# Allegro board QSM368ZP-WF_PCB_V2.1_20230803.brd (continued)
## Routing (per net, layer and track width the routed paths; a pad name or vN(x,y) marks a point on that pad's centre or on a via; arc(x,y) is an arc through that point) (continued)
100OHM_LAN0_RJ45_D2P_A: length 18.2
  BOTTOM w0.092: J0901.4 108.46,9.34 108.35,9.22 107.87,9.22 107.55,9.55 107.55,11.19 106.73,12 106.73,18.41 103.85,21.3 103.85,23.2 103.92,23.28 103.92,24.29 U0901.19
100OHM_LAN0_RJ45_D3M_A: length 18.2
  BOTTOM w0.092: U0901.23 99.92,24.25 99.92,23.28 100.32,22.88 100.32,22.6 100.2,22.49 100.2,22.21 100.32,22.09 100.32,21.58 105.29,16.61 105.29,9.67 105.17,9.55 104.94,9.55 J0901.8
100OHM_LAN0_RJ45_D3P_A: length 18.2
  BOTTOM w0.092: J0901.7 105.4,9.48 105.5,9.58 105.5,16.7 100.53,21.67 100.53,22.88 100.92,23.28 100.92,24.25 U0901.22
100OHM_MIPI_CSI_RX_CLK0N: length 55.3
  TOP w0.092: R0258.1 93.53,91.67 93.62,91.58 U0207.1 93.62,91.08 93.81,90.89 93.81,89.99 93.66,89.83 93.47,89.83 93.37,89.93 93.37,90.21 93.28,90.3 93.1,90.3 93.01,90.21 93.01,89.93 92.91,89.83 92.73,89.83 92.64,89.93 92.64,90.21 92.55,90.3 92.36,90.3 92.27,90.21 92.27,89.93 92.18,89.83 91.89,89.83 91.8,89.93 91.8,90.64 91.59,90.85 91.23,90.85 91.01,90.64 91.01,90.07 90.92,89.97 88.33,89.97 86.66,88.3 86.66,77.84 84.63,75.82 72.45,75.82 71.19,74.56 70.64,74.56 70.55,74.65 70.55,75.19 70.33,75.4 69.97,75.4 69.76,75.19 69.76,74.65 69.67,74.56 69.48,74.56 69.39,74.65 69.39,75.19 69.18,75.4 68.82,75.4 68.6,75.19 68.6,74.65 68.51,74.56 68.33,74.56 68.24,74.65 68.24,75.19 68.02,75.4 67.66,75.4 67.45,75.19 67.45,74.65 67.36,74.56 66.41,74.56 66.19,74.34 66.19,74.04 66.07,73.92 66.07,73.65 66.19,73.53 66.19,73.25 66.07,73.14 66.07,72.86 66.19,72.74 66.19,72.47 66.1,72.38 65.1,72.38 65.01,72.28 64.78,72.28 64.6,72.47 64.6,73.11 64.77,73.28 U1301.2
100OHM_MIPI_CSI_RX_CLK0N1: length 5.8
  TOP w0.092: R0258.2 93.5,92.58 93.62,92.7 U0207.3 93.62,93.17 94.06,93.61 94.06,93.79 93.95,93.9 93.63,93.9 93.51,93.78 93.23,93.78 93.11,93.9 92.84,93.9 92.72,93.78 92.44,93.78 92.33,93.9 92.05,93.9 91.84,94.11 91.84,94.36 91.75,94.45 J0201.20
100OHM_MIPI_CSI_RX_CLK0P: length 52.9
  TOP w0.092: R0257.1 94.28,91.67 94.17,91.58 U0207.2 94.17,91.08 94.03,90.92 94.03,89.9 93.75,89.62 91.81,89.62 91.59,89.84 91.59,90.55 91.5,90.64 91.32,90.64 91.22,90.55 91.22,89.98 91.01,89.77 88.41,89.77 86.87,88.22 86.87,77.76 84.72,75.61 72.53,75.61 71.28,74.35 70.55,74.35 70.34,74.56 70.34,75.1 70.25,75.19 70.06,75.19 69.97,75.1 69.97,74.56 69.75,74.35 69.4,74.35 69.18,74.56 69.18,75.1 69.09,75.19 68.91,75.19 68.81,75.1 68.81,74.56 68.6,74.35 68.24,74.35 68.03,74.56 68.03,75.1 67.93,75.19 67.75,75.19 67.66,75.1 67.66,74.56 67.44,74.35 66.49,74.35 66.4,74.26 66.4,72.38 66.19,72.17 65.19,72.17 64.55,71.53 U1301.3
100OHM_MIPI_CSI_RX_CLK0P1: length 8.3
  TOP w0.092: R0257.2 94.29,92.58 94.17,92.69 U0207.4 94.17,93.43 94.27,93.52 94.27,93.88 94.04,94.11 92.14,94.11 92.05,94.2 J0201.19
100OHM_MIPI_CSI_RX_CLK1N: length 56.8
  TOP w0.092: 83.88,91.78 82.83,91.78 82.72,91.67 82.72,91.2 82.39,90.86 82.39,90.33 81.99,89.94 81.69,89.94 80.8,90.83 80.67,90.83 80.54,90.69 80.54,90.56 81.43,89.68 81.43,89.38 81.17,89.12 80.87,89.12 79.63,90.36 79.5,90.36 79.37,90.23 79.37,90.1 80.61,88.86 80.61,88.56 79.69,87.64 79.38,87.64 78.95,88.07 78.82,88.07 78.69,87.94 78.69,87.81 79.21,87.29 79.21,86.72 79,86.5 78.2,86.5 78.11,86.41 78.11,86.23 78.2,86.13 79,86.13 79.21,85.92 79.21,85.56 79,85.35 78.2,85.35 78.11,85.25 78.11,85.07 78.2,84.98 79,84.98 79.21,84.76 79.21,84.41 79,84.19 78.2,84.19 78.11,84.1 78.11,83.91 78.2,83.82 79,83.82 79.21,83.61 79.21,83.06 77.19,81.04 69.94,81.04 64.8,75.9 61.17,75.9 60.94,75.67 60.94,75.54 61.06,75.42 61.06,75.29 60.93,75.16 60.8,75.16 60.68,75.28 60.55,75.28 60.42,75.15 60.42,75.02 60.54,74.9 60.54,74.77 60.41,74.64 60.28,74.64 60.16,74.76 60.03,74.76 59.76,74.49 59.76,74.16 59.88,74.04 59.88,73.77 59.76,73.65 59.76,73.37 59.88,73.25 59.88,72.98 59.76,72.86 59.76,72.58 59.12,71.95 59.12,70.85 59.62,70.36 60.29,70.36 60.46,70.53 60.62,70.53 61.09,70.06 61.26,70.06 61.46,69.86 61.46,69.69 61.67,69.47 U1301.6
100OHM_MIPI_CSI_RX_CLK1N1: length 4.5
  TOP w0.092: R0264.2 82.82,92.67 82.72,92.77 82.72,93.45 82.56,93.61 81.89,93.61 81.63,93.87 81.63,94.03 81.44,94.23 81.27,94.23 81.08,94.42 J0202.20
100OHM_MIPI_CSI_RX_CLK1P: length 54
  TOP w0.092: U1301.9 60.55,69.67 60.08,70.15 59.53,70.15 58.91,70.76 58.91,72.04 59.55,72.67 59.55,74.58 61.09,76.11 64.71,76.11 69.85,81.25 77.1,81.25 79,83.15 79,83.52 78.91,83.61 78.11,83.61 77.9,83.83 77.9,84.19 78.11,84.4 78.91,84.4 79,84.49 79,84.68 78.91,84.77 78.11,84.77 77.9,84.98 77.9,85.34 78.11,85.56 78.91,85.56 79,85.65 79,85.83 78.91,85.92 78.11,85.92 77.9,86.14 77.9,86.5 78.11,86.71 78.91,86.71 79,86.8 79,87.2 78.48,87.73 78.48,88.03 78.73,88.28 79.04,88.28 79.47,87.85 79.6,87.85 80.4,88.65 80.4,88.78 79.16,90.01 79.16,90.31 79.42,90.57 79.72,90.57 80.96,89.33 81.09,89.33 81.22,89.46 81.22,89.59 80.33,90.48 80.33,90.78 80.59,91.04 80.89,91.04 81.77,90.15 81.9,90.15 82.17,90.42 U0208.1 82.17,91.68 82.08,91.78 81.03,91.78
100OHM_MIPI_CSI_RX_CLK1P1: length 7.1
  TOP w0.092: J0202.19 81.38,95.92 80.78,95.33 80.78,94.43 81.8,93.4 82.05,93.4 82.17,93.28 U0208.3 82.17,92.78 82.08,92.67 R0263.2
100OHM_MIPI_CSI_RX_D0N: length 56.9
  TOP w0.092: U1301.7 62.15,72.75 61.77,72.37 61.77,72.18 61.85,72.1 62.15,72.1 62.89,72.84 62.89,74.09 63.51,74.71 65.31,74.71 67.06,76.46 68.2,76.46 68.29,76.55 68.29,76.89 68.51,77.1 68.87,77.1 69.08,76.89 69.08,76.35 69.17,76.26 69.36,76.26 69.45,76.35 69.45,76.89 69.66,77.1 70.02,77.1 70.24,76.89 70.24,76.35 70.33,76.26 70.51,76.26 70.6,76.35 70.6,76.89 70.82,77.1 71.18,77.1 71.39,76.89 71.39,76.35 71.48,76.26 71.61,76.26 71.88,76.53 72.04,76.53 72.13,76.62 72.13,77.26 72.34,77.47 72.7,77.47 72.92,77.26 72.92,76.62 73.01,76.53 73.19,76.53 73.28,76.62 73.28,77.26 73.5,77.47 73.86,77.47 74.07,77.26 74.07,76.62 74.16,76.53 74.35,76.53 74.44,76.62 74.44,77.26 74.65,77.47 75.01,77.47 75.23,77.26 75.23,76.62 75.32,76.53 84.26,76.53 85.89,78.15 85.89,88.56 86.13,88.8 86.13,88.93 85.89,89.16 85.89,89.29 86.02,89.42 86.15,89.42 86.39,89.19 86.52,89.19 86.65,89.32 86.65,89.45 86.41,89.68 86.41,89.81 86.54,89.94 86.67,89.94 86.91,89.71 87.04,89.71 87.17,89.84 87.17,89.97 86.93,90.2 86.93,90.33 87.06,90.46 87.19,90.46 87.43,90.23 87.56,90.23 88.06,90.73 89.84,90.73 90,90.9 90,91.38 U0209.1 89.92,91.58 89.83,91.67 R0260.1
100OHM_MIPI_CSI_RX_D0N1: length 4.4
  TOP w0.092: J0201.22 91.15,94.47 91.24,94.39 91.24,94.04 91.14,93.94 90.48,93.94 90.27,93.72 90.27,93.31 90.2,93.25 90.03,93.25 89.92,93.15 U0209.3 89.92,92.67 89.83,92.58 R0260.2
100OHM_MIPI_CSI_RX_D0P: length 54.4
  TOP w0.092: R0259.1 90.57,91.67 90.47,91.58 U0209.2 90.47,91.08 89.92,90.53 88.15,90.53 86.1,88.47 86.1,78.06 84.35,76.31 75.23,76.31 75.02,76.53 75.02,77.17 74.93,77.27 74.74,77.27 74.65,77.17 74.65,76.53 74.43,76.31 74.08,76.31 73.86,76.53 73.86,77.17 73.77,77.27 73.59,77.27 73.49,77.17 73.49,76.53 73.28,76.31 72.92,76.31 72.71,76.53 72.71,77.17 72.61,77.27 72.43,77.27 72.34,77.17 72.34,76.53 72.12,76.31 71.96,76.31 71.7,76.05 71.4,76.05 71.18,76.27 71.18,76.8 71.09,76.89 70.91,76.89 70.81,76.8 70.81,76.27 70.6,76.05 70.24,76.05 70.03,76.27 70.03,76.8 69.93,76.89 69.75,76.89 69.66,76.8 69.66,76.27 69.44,76.05 69.09,76.05 68.87,76.27 68.87,76.8 68.78,76.89 68.59,76.89 68.5,76.8 68.5,76.47 68.29,76.25 67.15,76.25 65.4,74.5 63.6,74.5 63.1,74 63.1,72.75 62.24,71.89 61.99,71.89 61.92,71.82 61.92,71.58 61.73,71.38 U1301.8
100OHM_MIPI_CSI_RX_D0P1: length 7
  TOP w0.092: J0201.21 91.45,93.95 91.22,93.72 90.57,93.72 90.47,93.63 U0209.4 90.47,92.67 90.57,92.58 R0259.2
100OHM_MIPI_CSI_RX_D1N: length 52.5
  TOP w0.092: U1301.4 63.75,70.65 63.96,70.44 65.16,70.44 66.61,71.89 67.09,71.89 68.98,73.78 71.88,73.78 73.19,75.08 84.93,75.08 87.39,77.54 87.39,86.51 90.01,89.14 95.05,89.14 95.17,89.25 95.44,89.25 95.56,89.14 95.84,89.14 96.38,89.67 96.38,89.84 96.57,90.03 96.74,90.03 96.93,90.23 96.93,90.4 97.13,90.59 97.29,90.59 97.49,90.79 97.49,90.94 97.33,91.1 U0206.1 97.33,91.55 97.2,91.67 R0256.1
100OHM_MIPI_CSI_RX_D1N1: length 8.9
  TOP w0.092: J0201.10 94.75,95.75 95.05,96.05 95.33,96.05 95.44,95.93 95.72,95.93 95.84,96.05 96.11,96.05 96.23,95.93 96.51,95.93 96.63,96.05 97.17,96.05 97.92,95.31 97.92,94.91 97.8,94.79 97.8,94.51 97.92,94.39 97.92,94.02 97.67,93.77 97.67,93.39 97.57,93.3 97.5,93.3 97.33,93.13 U0206.3 97.33,92.67 97.22,92.58 R0256.2
100OHM_MIPI_CSI_RX_D1P: length 52.9
  TOP w0.092: R0255.1 98,91.67 97.88,91.55 U0206.2 97.88,91.1 97.7,90.92 97.7,90.7 95.92,88.92 90.1,88.92 87.6,86.42 87.6,77.45 85.02,74.88 73.28,74.88 71.97,73.56 69.06,73.56 67.17,71.67 66.7,71.67 65.25,70.22 63.88,70.22 63.54,70.56 63.54,72.01 63.45,72.1 63.12,72.1 62.95,71.92 U1301.5
100OHM_MIPI_CSI_RX_D1P1: length 8.6
  TOP w0.092: R0255.2 98,92.58 97.88,92.7 U0206.4 97.88,93.68 98.12,93.93 98.12,95.4 97.26,96.26 95.49,96.26 95.05,96.7 J0201.9
100OHM_MIPI_CSI_RX_D2N: length 53.9
  TOP w0.092: 80.17,91.78 79.15,91.78 79.03,91.65 U0201.2 79.03,91.2 78.85,91.03 78.85,90.78 78.64,90.56 77.2,90.56 77.11,90.47 77.11,90.26 77.2,90.17 78.33,90.17 78.55,89.95 78.55,89.6 78.33,89.38 77.2,89.38 77.11,89.29 77.11,89.1 77.2,89.01 77.98,89.01 78.2,88.8 78.2,88.44 77.98,88.22 77.2,88.22 77.11,88.13 77.11,84.64 76.55,84.08 76.55,83.95 77.3,83.2 77.3,82.9 77.05,82.65 76.74,82.65 76,83.39 75.87,83.39 75.74,83.26 75.74,83.13 76.48,82.39 76.48,82.08 76.23,81.83 75.92,81.83 75.18,82.57 75.05,82.57 74.22,81.75 69.65,81.75 64.75,76.85 64.17,76.85 63.88,77.14 63.7,77.14 63.6,77.05 63.6,76.84 63.39,76.62 63.03,76.62 62.82,76.84 62.82,77.05 62.72,77.14 62.54,77.14 62.45,77.05 62.45,76.84 62.23,76.62 61.87,76.62 61.66,76.84 61.66,77.05 61.57,77.14 61.38,77.14 61.29,77.05 61.29,76.84 61.08,76.62 60.88,76.62 60.71,76.46 60.41,76.46 59.71,77.16 59.58,77.16 59.45,77.03 59.45,76.9 60.15,76.2 60.15,75.9 59.9,75.65 59.59,75.65 58.35,76.89 58.22,76.89 58.09,76.76 58.09,76.63 59.33,75.39 59.33,75.08 59.08,74.83 58.77,74.83 58.52,75.09 58.39,75.09 58.25,74.96 58.25,74.83 58.51,74.57 58.51,74.26 58.36,74.11 58.36,72.47 58.5,72.33 58.77,72.33 58.95,72.5 U1301.16
100OHM_MIPI_CSI_RX_D2N1: length 7.5
  TOP w0.092: R0266.2 79.12,92.67 79.03,92.78 U0201.4 79.03,93.28 78.88,93.42 78.88,94.17 78.99,94.29 78.99,94.57 78.88,94.69 78.88,94.96 78.99,95.08 78.99,95.36 78.88,95.47 78.88,95.75 79.27,96.14 79.54,96.14 79.66,96.02 79.94,96.02 80.06,96.14 80.38,96.14 80.47,96.05 J0202.22
100OHM_MIPI_CSI_RX_D2P: length 53.5
  TOP w0.092: U1301.17 58.15,74.2 58.3,74.35 58.3,74.48 58.04,74.74 58.04,75.04 58.3,75.3 58.6,75.3 58.86,75.04 58.99,75.04 59.12,75.17 59.12,75.3 57.88,76.55 57.88,76.85 58.13,77.1 58.43,77.1 59.68,75.86 59.81,75.86 59.94,75.99 59.94,76.12 59.24,76.81 59.24,77.12 59.5,77.37 59.8,77.37 60.5,76.67 60.63,76.67 60.79,76.83 60.99,76.83 61.08,76.93 61.08,77.14 61.3,77.35 61.65,77.35 61.87,77.14 61.87,76.93 61.96,76.83 62.15,76.83 62.24,76.93 62.24,77.14 62.45,77.35 62.81,77.35 63.03,77.14 63.03,76.93 63.12,76.83 63.3,76.83 63.39,76.93 63.39,77.14 63.61,77.35 63.97,77.35 64.26,77.06 64.66,77.06 69.56,81.96 74.14,81.96 74.96,82.78 75.27,82.78 76.01,82.04 76.14,82.04 76.27,82.17 76.27,82.3 75.53,83.04 75.53,83.35 75.78,83.6 76.08,83.6 76.83,82.86 76.96,82.86 77.09,82.99 77.09,83.12 76.34,83.86 76.34,84.17 76.9,84.72 76.9,88.22 77.11,88.43 77.9,88.43 77.99,88.53 77.99,88.71 77.9,88.8 77.11,88.8 76.9,89.02 76.9,89.38 77.11,89.59 78.25,89.59 78.34,89.68 78.34,89.87 78.25,89.96 77.11,89.96 76.9,90.17 76.9,90.56 77.11,90.78 78.55,90.78 78.64,90.87 78.64,91.03 78.47,91.2 U0201.1 78.47,91.65 78.35,91.78 77.33,91.78
100OHM_MIPI_CSI_RX_D2P1: length 7.8
  TOP w0.092: R0265.2 78.38,92.67 78.47,92.78 U0201.3 78.47,93.25 78.67,93.44 78.67,95.84 79.18,96.35 80.42,96.35 80.78,96.7 80.78,97.75
100OHM_MIPI_CSI_RX_D3N: length 52.3
  TOP w0.092: 84.72,91.78 85.78,91.78 85.88,91.68 U0210.1 85.88,90.88 85.09,90.09 85.09,83.74 84.8,83.45 80.6,83.45 77.16,80.01 76.8,80.01 76.58,79.8 76.58,79.3 76.49,79.21 76.31,79.21 76.22,79.3 76.22,79.8 76,80.01 75.64,80.01 75.43,79.8 75.43,79.3 75.34,79.21 75.15,79.21 75.06,79.3 75.06,79.8 74.85,80.01 74.09,80.01 73.97,80.13 73.69,80.13 73.58,80.01 73.3,80.01 73.18,80.13 72.91,80.13 72.79,80.01 72.2,80.01 71.85,79.66 71.67,79.66 71.58,79.75 71.58,80.28 71.36,80.5 70.1,80.5 69.85,80.25 69.85,79.95 70.9,78.9 70.9,78.77 70.77,78.64 70.64,78.64 69.59,79.69 69.29,79.69 69.04,79.43 69.04,79.13 70.08,78.08 70.08,77.95 69.95,77.82 69.82,77.82 68.78,78.87 68.47,78.87 68.22,78.62 68.22,78.31 68.46,78.07 68.46,77.94 68.33,77.81 68.2,77.81 67.96,78.05 67.65,78.05 65.01,75.41 62.74,75.41 62.5,75.17 62.24,75.17 62.1,75.03 62.1,74.78 61.97,74.65 61.84,74.65 61.76,74.73 61.63,74.73 61.5,74.6 61.5,74.47 61.58,74.39 61.58,74.26 61.34,74.01 61.34,73.55 61.22,73.43 61.22,73.16 61.34,73.04 61.34,72.76 60.93,72.35 60.48,72.35 60.38,72.45 60.38,72.58 60.55,72.75 U1301.11
100OHM_MIPI_CSI_RX_D3N1: length 9.1
  TOP w0.092: R0262.2 85.78,92.67 85.88,92.78 U0210.3 85.88,93.25 86.06,93.43 86.06,93.68 86.36,93.98 86.81,93.98 87.17,94.34 87.17,94.74 87.05,94.86 87.05,95.14 87.17,95.26 87.17,95.53 86.71,95.99 86.42,95.99 86.3,95.87 86.02,95.87 85.9,95.99 85.63,95.99 85.51,95.87 85.23,95.87 85.12,95.99 84.84,95.99 84.64,95.79 84.64,95.63 84.45,95.43 84.28,95.43 84.08,95.22 J0202.10
100OHM_MIPI_CSI_RX_D3P: length 52.1
  TOP w0.092: 87.58,91.78 86.55,91.78 86.42,91.65 86.42,91.13 85.3,90 85.3,83.65 84.89,83.24 80.69,83.24 77.25,79.8 76.89,79.8 76.79,79.71 76.79,79.22 76.58,79 76.22,79 76.01,79.22 76.01,79.71 75.91,79.8 75.73,79.8 75.64,79.71 75.64,79.22 75.42,79 75.07,79 74.85,79.22 74.85,79.71 74.76,79.8 72.29,79.8 71.94,79.45 71.58,79.45 71.37,79.67 71.37,80.2 71.28,80.29 70.19,80.29 70.06,80.16 70.06,80.03 71.11,78.99 71.11,78.69 70.86,78.43 70.55,78.43 69.51,79.48 69.38,79.48 69.25,79.35 69.25,79.22 70.29,78.17 70.29,77.87 70.04,77.61 69.73,77.61 68.69,78.66 68.56,78.66 68.43,78.53 68.43,78.4 68.67,78.15 68.67,77.85 68.42,77.6 68.12,77.6 67.87,77.84 67.74,77.84 65.1,75.2 62.83,75.2 61.55,73.92 61.55,72.67 61.02,72.14 60.49,72.14 60.35,72 60.35,71.59 60.13,71.38 U1301.12
100OHM_MIPI_CSI_RX_D3P1: length 9.2
  TOP w0.092: J0202.9 84.38,96.85 85.03,96.2 86.8,96.2 87.38,95.62 87.38,94.25 86.9,93.78 86.45,93.78 86.27,93.59 86.27,93.41 86.42,93.25 86.42,92.8 86.55,92.67 R0261.2
100OHM_MIPI_DSI_TX0_CLKN: length 39.2
  TOP w0.092: U1301.37 51.75,75.37 56.34,79.96 56.34,84.81 56.25,84.9 55.44,84.9 55.23,85.11 55.23,85.47 55.44,85.69 56.25,85.69 56.34,85.78 56.34,85.96 56.25,86.05 55.44,86.05 55.23,86.27 55.23,86.63 55.44,86.84 56.25,86.84 56.34,86.93 56.34,87.12 56.25,87.21 55.44,87.21 55.23,87.42 55.23,87.78 55.44,88 56.25,88 56.34,88.09 56.34,88.34 56.25,88.43 55.87,88.43 55.65,88.65 55.65,89.01 55.87,89.22 56.25,89.22 56.34,89.31 56.34,89.72 58.9,92.28 59.45,92.28 61.05,93.88 63.13,93.88 63.25,93.99 63.25,96.17 63.35,96.28 J0403.17
100OHM_MIPI_DSI_TX0_CLKP: length 39
  TOP w0.092: J0403.18 63.85,96.07 63.77,96.15 63.52,96.15 63.46,96.09 63.46,93.9 63.22,93.67 61.14,93.67 59.54,92.06 58.99,92.06 56.55,89.63 56.55,89.23 56.34,89.01 55.95,89.01 55.86,88.92 55.86,88.74 55.95,88.64 56.34,88.64 56.55,88.43 56.55,88 56.34,87.79 55.53,87.79 55.44,87.69 55.44,87.51 55.53,87.42 56.34,87.42 56.55,87.2 56.55,86.85 56.34,86.63 55.53,86.63 55.44,86.54 55.44,86.36 55.53,86.26 56.34,86.26 56.55,86.05 56.55,85.69 56.34,85.47 55.53,85.47 55.44,85.38 55.44,85.2 55.53,85.11 56.34,85.11 56.55,84.89 56.55,79.88 51.96,75.28 51.96,72.69 52.15,72.5 52.42,72.5 52.55,72.63 U1301.36
100OHM_MIPI_DSI_TX0_D0N: length 39.3
  TOP w0.092: U1301.47 48.55,74.17 53.64,79.26 53.64,83.15 53.55,83.25 53.29,83.25 53.08,83.46 53.08,83.82 53.29,84.03 53.55,84.03 53.64,84.13 53.64,84.31 53.55,84.4 53.27,84.4 53.05,84.62 53.05,84.97 53.27,85.19 53.55,85.19 53.64,85.28 53.64,85.76 53.55,85.86 52.62,85.86 52.4,86.07 52.4,86.43 52.62,86.64 53.55,86.64 53.64,86.74 53.64,86.92 53.55,87.01 52.62,87.01 52.4,87.23 52.4,87.58 52.62,87.8 53.55,87.8 53.64,87.89 53.64,88.08 53.55,88.17 52.62,88.17 52.4,88.38 52.4,88.74 52.62,88.96 53.55,88.96 53.64,89.05 53.64,89.24 56.44,92.04 56.44,92.2 56.63,92.4 56.8,92.4 57,92.6 57,92.76 57.19,92.96 57.36,92.96 57.55,93.15 57.55,93.32 57.75,93.51 57.91,93.51 58.11,93.71 58.81,93.71 59.24,94.14 59.24,96.13 59.15,96.22 58.95,96.22 58.85,96.12 J0403.8
100OHM_MIPI_DSI_TX0_D0P: length 39.2
  TOP w0.092: U1301.46 49.35,72.57 49.26,72.47 48.85,72.47 48.76,72.57 48.76,74.08 53.85,79.17 53.85,83.24 53.63,83.46 53.38,83.46 53.28,83.55 53.28,83.73 53.38,83.82 53.63,83.82 53.85,84.04 53.85,84.4 53.63,84.61 53.35,84.61 53.26,84.7 53.26,84.89 53.35,84.98 53.63,84.98 53.85,85.19 53.85,85.85 53.63,86.07 52.7,86.07 52.61,86.16 52.61,86.34 52.7,86.43 53.63,86.43 53.85,86.65 53.85,87.01 53.63,87.22 52.7,87.22 52.61,87.31 52.61,87.5 52.7,87.59 53.63,87.59 53.85,87.8 53.85,88.16 53.63,88.38 52.7,88.38 52.61,88.47 52.61,88.65 52.7,88.75 53.63,88.75 53.85,88.96 53.85,89.15 58.2,93.5 58.9,93.5 59.45,94.05 59.45,96.34 59.35,96.44 J0403.9
100OHM_MIPI_DSI_TX0_D1N: length 38.5
  TOP w0.092: J0403.11 60.35,96.3 60.25,96.2 60.25,94.17 59.09,93.01 58.51,93.01 54.34,88.84 54.34,83.97 54.55,83.75 55.5,83.75 55.59,83.66 55.59,83.47 55.5,83.38 54.55,83.38 54.34,83.17 54.34,82.81 54.55,82.59 55.5,82.59 55.59,82.5 55.59,82.32 55.5,82.23 54.55,82.23 54.34,82.01 54.34,81.65 54.55,81.44 55.5,81.44 55.59,81.35 55.59,81.16 55.5,81.07 54.55,81.07 54.34,80.86 54.34,80.41 54.55,80.2 55.1,80.2 55.19,80.1 55.19,79.92 55.1,79.83 54.55,79.83 54.34,79.61 54.34,78.96 50.15,74.77 U1301.42
100OHM_MIPI_DSI_TX0_D1P: length 38.6
  TOP w0.092: J0403.12 60.85,96.12 60.76,96.21 60.56,96.21 60.46,96.11 60.46,94.08 59.18,92.8 58.6,92.8 54.55,88.75 54.55,84.05 54.64,83.96 55.59,83.96 55.8,83.75 55.8,83.39 55.59,83.17 54.64,83.17 54.55,83.08 54.55,82.9 54.64,82.8 55.59,82.8 55.8,82.59 55.8,82.23 55.59,82.02 54.64,82.02 54.55,81.92 54.55,81.74 54.64,81.65 55.59,81.65 55.8,81.43 55.8,81.08 55.59,80.86 54.64,80.86 54.55,80.77 54.55,80.5 54.64,80.41 55.19,80.41 55.4,80.19 55.4,79.83 55.19,79.62 54.64,79.62 54.55,79.53 54.55,78.88 50.36,74.69 50.36,72.54 50.45,72.45 50.83,72.45 50.95,72.58 U1301.41
100OHM_MIPI_DSI_TX0_D2N: length 39.3
  TOP w0.092: J0403.14 61.85,96.05 61.99,96.19 62.66,96.19 62.96,96.49 62.96,98.47 63.05,98.56 64.65,98.56 64.74,98.47 64.74,96.69 64.24,96.19 64.24,93.99 63.42,93.17 61.5,93.17 59.91,91.58 59.28,91.58 57.04,89.34 57.04,79.67 53.35,75.97 U1301.32
100OHM_MIPI_DSI_TX0_D2P: length 39.3
  TOP w0.092: J0403.15 62.35,96.5 62.45,96.4 62.58,96.4 62.75,96.58 62.75,98.56 62.97,98.78 64.73,98.78 64.95,98.56 64.95,96.6 64.45,96.1 64.45,93.9 63.51,92.97 61.59,92.97 60,91.38 59.37,91.38 57.25,89.25 57.25,79.58 53.56,75.89 53.56,72.69 53.65,72.6 54.06,72.6 54.15,72.69 U1301.31
100OHM_MIPI_DSI_TX0_D3N: length 39
  TOP w0.092: J0403.20 64.85,96.1 64.94,96.19 65.15,96.19 65.24,96.1 65.24,94 63.66,92.42 61.85,92.42 60.3,90.88 59.62,90.88 57.74,88.99 57.74,88.45 57.95,88.24 58.52,88.24 58.62,88.15 58.62,87.96 58.52,87.87 57.95,87.87 57.74,87.66 57.74,87.3 57.95,87.08 58.52,87.08 58.62,86.99 58.62,86.81 58.52,86.71 57.95,86.71 57.74,86.5 57.74,86.14 57.95,85.93 58.5,85.93 58.59,85.83 58.59,85.65 58.5,85.56 57.95,85.56 57.74,85.34 57.74,84.99 57.95,84.77 58.52,84.77 58.62,84.68 58.62,84.49 58.52,84.4 57.95,84.4 57.74,84.19 57.74,83.83 57.95,83.61 58.52,83.61 58.62,83.52 58.62,83.34 58.52,83.25 57.95,83.25 57.74,83.03 57.74,79.34 54.95,76.55 54.95,76.13 54.83,76.01 54.83,75.74 54.95,75.62 54.95,75.34 54.83,75.23 54.83,74.95 54.95,74.83 54.95,74.56 54.83,74.44 54.83,74.16 54.95,74.04 U1301.27
100OHM_MIPI_DSI_TX0_D3P: length 39
  TOP w0.092: J0403.21 65.45,97.47 65.45,93.91 63.75,92.22 61.94,92.22 60.39,90.67 59.71,90.67 57.95,88.9 57.95,88.54 58.04,88.45 58.61,88.45 58.83,88.23 58.83,87.88 58.61,87.66 58.04,87.66 57.95,87.57 57.95,87.38 58.04,87.29 58.61,87.29 58.83,87.08 58.83,86.72 58.61,86.5 58.04,86.5 57.95,86.41 57.95,86.23 58.04,86.14 58.59,86.14 58.8,85.92 58.8,85.56 58.59,85.35 58.04,85.35 57.95,85.26 57.95,85.07 58.04,84.98 58.61,84.98 58.83,84.77 58.83,84.41 58.61,84.19 58.04,84.19 57.95,84.1 57.95,83.92 58.04,83.82 58.61,83.82 58.83,83.61 58.83,83.25 58.61,83.04 58.04,83.04 57.95,82.94 57.95,79.25 55.16,76.46 55.16,72.54 55.25,72.45 55.57,72.45 55.75,72.63 U1301.26
100OHM_MIPI_DSI_TX1_CLKN: length 60.3
  TOP w0.092: v1(35.67,93.47) 35.62,93.53 D0506.2 35.92,94.25 36.15,94.47 R0575.1 ; U1301.33 52.55,68.72 52.64,68.62 v1(52.65,68.62)
  INNER LAYER 3 w0.074: v1(52.65,68.62) 52.8,68.78 52.8,69 52.67,69.12 52.67,69.34 52.8,69.47 52.8,69.69 52.67,69.82 52.67,70.04 52.8,70.17 52.8,70.39 52.67,70.52 52.67,70.74 52.8,70.86 52.8,71.07 52.73,71.14 52.27,71.14 52.08,71.33 52.08,71.65 52.27,71.84 52.73,71.84 52.8,71.91 52.8,72.13 52.73,72.2 49.09,72.2 45.75,75.54 45.75,75.87 45.68,75.94 44.79,75.94 44.6,76.13 44.6,76.44 44.79,76.64 45.68,76.64 45.75,76.71 45.75,76.86 45.68,76.93 44.79,76.93 44.6,77.12 44.6,77.44 44.79,77.63 45.68,77.63 45.75,77.7 45.75,77.85 45.68,77.92 44.79,77.92 44.6,78.12 44.6,78.43 44.79,78.62 45.68,78.62 45.75,78.69 45.75,78.84 45.68,78.92 44.79,78.92 44.6,79.11 44.6,79.42 44.79,79.61 45.68,79.61 45.75,79.69 45.75,79.83 45.68,79.91 44.79,79.91 44.6,80.1 44.6,80.41 44.79,80.6 45.68,80.6 45.75,80.68 45.75,80.83 45.68,80.9 44.79,80.9 44.6,81.09 44.6,81.41 44.79,81.6 45.68,81.6 45.75,81.67 45.75,81.82 45.68,81.89 44.79,81.89 44.6,82.08 44.6,82.4 44.79,82.59 45.68,82.59 45.75,82.66 45.75,82.81 45.68,82.88 44.79,82.88 44.6,83.08 44.6,83.39 44.79,83.58 45.68,83.58 45.75,83.65 45.75,83.8 45.68,83.88 44.79,83.88 44.6,84.07 44.6,84.38 44.79,84.57 45.68,84.57 45.75,84.65 45.75,84.79 45.68,84.87 44.79,84.87 44.6,85.06 44.6,85.37 44.79,85.56 45.68,85.56 45.75,85.64 45.75,85.84 38.38,93.21 38.21,93.21 38.05,93.36 38.05,93.54 37.89,93.7 37.67,93.7 37.54,93.57 37.32,93.57 37.2,93.7 36.86,93.7 36.74,93.57 36.51,93.57 36.39,93.7 35.9,93.7 v1(35.67,93.47)
100OHM_MIPI_DSI_TX1_CLKN_1: length 8.5
  TOP w0.092: R0575.2 35.75,95.38 35.62,95.5 D0506.4 35.62,95.96 35.53,96.05 35.44,96.05 35.3,96.19 35.3,96.42 35.05,96.67 34.49,96.67 34.37,96.79 34.1,96.79 33.98,96.67 33.7,96.67 33.25,96.22 33.25,95.94 33.13,95.82 33.13,95.54 33.25,95.42 33.25,95.15 32.99,94.89 32.4,94.89 32.28,95 32.01,95 31.89,94.89 31.61,94.89 31.44,95.06 31.44,95.21 31.48,95.25 J0501.30
100OHM_MIPI_DSI_TX1_CLKP: length 61
  TOP w0.092: R0574.1 34.55,94.47 34.78,94.25 D0506.1 35.08,93.53 v1(35.02,93.47) ; v1(53.27,68.42) 53.35,68.35 U1301.29
  INNER LAYER 3 w0.074: v1(35.02,93.47) 35.02,93.5 35.42,93.9 37.98,93.9 45.95,85.92 45.95,85.56 45.76,85.36 44.87,85.36 44.8,85.29 44.8,85.14 44.87,85.07 45.76,85.07 45.95,84.88 45.95,84.56 45.76,84.37 44.87,84.37 44.8,84.3 44.8,84.15 44.87,84.08 45.76,84.08 45.95,83.89 45.95,83.57 45.76,83.38 44.87,83.38 44.8,83.31 44.8,83.16 44.87,83.08 45.76,83.08 45.95,82.89 45.95,82.58 45.76,82.39 44.87,82.39 44.8,82.31 44.8,82.17 44.87,82.09 45.76,82.09 45.95,81.9 45.95,81.59 45.76,81.4 44.87,81.4 44.8,81.32 44.8,81.17 44.87,81.1 45.76,81.1 45.95,80.91 45.95,80.6 45.76,80.4 44.87,80.4 44.8,80.33 44.8,80.18 44.87,80.11 45.76,80.11 45.95,79.92 45.95,79.6 45.76,79.41 44.87,79.41 44.8,79.34 44.8,79.19 44.87,79.12 45.76,79.12 45.95,78.92 45.95,78.61 45.76,78.42 44.87,78.42 44.8,78.35 44.8,78.2 44.87,78.12 45.76,78.12 45.95,77.93 45.95,77.62 45.76,77.43 44.87,77.43 44.8,77.35 44.8,77.21 44.87,77.13 45.76,77.13 45.95,76.94 45.95,76.63 45.76,76.44 44.87,76.44 44.8,76.36 44.8,76.21 44.87,76.14 45.76,76.14 45.95,75.95 45.95,75.62 49.17,72.4 52.81,72.4 53,72.21 53,71.83 52.81,71.64 52.35,71.64 52.27,71.56 52.27,71.42 52.35,71.34 52.81,71.34 53,71.15 53,68.87 53.27,68.59 v1(53.27,68.42)
100OHM_MIPI_DSI_TX1_CLKP_1: length 8
  TOP w0.092: J0501.29 31.07,95.25 31.23,95.1 31.23,94.97 31.53,94.67 33.08,94.67 33.46,95.06 33.46,96.14 33.79,96.47 34.96,96.47 35.08,96.35 D0506.3 35.08,95.53 34.92,95.38 R0574.2
100OHM_MIPI_DSI_TX1_D0N: length 63.9
  TOP w0.092: v1(32.27,91.4) 32.27,91.45 32.17,91.55 D0502.2 32.17,92.15 32.27,92.25 R0573.1 ; v1(49.45,68.62) 49.44,68.62 49.35,68.72 U1301.43
  INNER LAYER 3 w0.074: v1(49.45,68.62) 49.6,68.78 49.6,69.67 49.44,69.83 48.94,69.83 48.86,69.75 48.86,69.07 48.67,68.88 48.36,68.88 48.17,69.07 48.17,69.75 48.09,69.83 47.37,69.83 47.17,70.02 47.17,71.12 46.98,71.31 46.88,71.31 45.64,70.08 45.37,70.08 45.15,70.3 45.15,70.57 46.38,71.8 46.38,71.91 46.28,72.01 46.17,72.01 44.94,70.78 44.67,70.78 44.45,71 44.45,71.27 45.68,72.51 45.68,72.61 45.58,72.72 45.47,72.72 44.24,71.48 43.97,71.48 43.75,71.7 43.75,71.97 44.98,73.21 44.98,73.31 44.87,73.42 44.77,73.42 44.04,72.68 43.77,72.68 43.54,72.91 43.54,73.18 44.28,73.91 44.28,74.01 43.4,74.89 43.4,86.44 42.82,87.02 42.72,87.02 42.12,86.42 41.85,86.42 41.63,86.64 41.63,86.91 42.23,87.51 42.23,87.61 42.08,87.77 41.97,87.77 41.39,87.18 41.12,87.18 40.9,87.4 40.9,87.68 41.48,88.26 41.48,88.36 41.37,88.47 41.27,88.47 40.69,87.88 40.42,87.88 40.19,88.11 40.19,88.38 40.78,88.96 40.78,89.06 40.67,89.17 40.57,89.17 39.98,88.59 39.71,88.59 39.49,88.81 39.49,89.08 40.08,89.66 40.08,89.77 39.97,89.87 39.87,89.87 39.28,89.29 39.01,89.29 38.79,89.51 38.79,89.78 39.37,90.36 39.37,90.47 37.92,91.92 36.64,91.92 36.52,91.8 36.29,91.8 36.17,91.92 35.95,91.92 35.82,91.8 35.6,91.8 35.47,91.92 35.25,91.92 35.12,91.8 34.9,91.8 34.78,91.92 34.55,91.92 34.43,91.8 34.21,91.8 34.08,91.92 33.86,91.92 33.73,91.8 33.51,91.8 33.38,91.92 33.16,91.92 33.04,91.8 32.81,91.8 32.69,91.92 32.11,91.92 32,91.82 32,91.47 32.07,91.4 v1(32.27,91.4)
100OHM_MIPI_DSI_TX1_D0N_1: length 5.2
  TOP w0.092: J0501.27 30.27,95.25 30.09,95.06 30.09,94.64 30.55,94.17 30.83,94.17 30.94,94.29 31.22,94.29 31.34,94.17 31.65,94.17 32.17,93.65 D0502.4 32.17,93.25 32.27,93.15 R0573.2
100OHM_MIPI_DSI_TX1_D0P: length 64.2
  TOP w0.092: U1301.39 50.15,68.35 v1(50.08,68.42) ; R0572.1 31.52,92.25 31.62,92.15 D0502.1 31.62,91.6 31.52,91.5 v1(31.52,91.4)
  INNER LAYER 3 w0.074: v1(50.08,68.42) 50.08,68.65 49.8,68.92 49.8,69.75 49.52,70.03 48.85,70.03 48.66,69.83 48.66,69.15 48.59,69.08 48.44,69.08 48.37,69.15 48.37,69.83 48.17,70.03 47.45,70.03 47.38,70.1 47.38,71.2 47.06,71.51 46.79,71.51 45.56,70.28 45.45,70.28 45.35,70.38 45.35,70.49 46.58,71.72 46.58,71.99 46.36,72.21 46.09,72.21 44.86,70.98 44.75,70.98 44.65,71.09 44.65,71.19 45.88,72.42 45.88,72.69 45.66,72.92 45.39,72.92 44.16,71.68 44.05,71.68 43.95,71.79 43.95,71.89 45.18,73.13 45.18,73.4 44.96,73.62 44.69,73.62 43.95,72.88 43.85,72.88 43.74,72.99 43.74,73.09 44.48,73.83 44.48,74.1 43.6,74.97 43.6,86.53 42.91,87.22 42.64,87.22 42.04,86.62 41.94,86.62 41.83,86.73 41.83,86.83 42.43,87.43 42.43,87.7 42.16,87.97 41.89,87.97 41.3,87.38 41.2,87.38 41.1,87.49 41.1,87.59 41.68,88.18 41.68,88.45 41.46,88.67 41.19,88.67 40.6,88.08 40.5,88.08 40.39,88.19 40.39,88.29 40.98,88.88 40.98,89.15 40.76,89.37 40.48,89.37 39.9,88.79 39.8,88.79 39.69,88.89 39.69,89 40.28,89.58 40.28,89.85 40.05,90.07 39.78,90.07 39.2,89.49 39.09,89.49 38.99,89.59 38.99,89.7 39.57,90.28 39.57,90.55 38,92.12 32.02,92.12 31.8,91.9 31.8,91.47 31.73,91.4 v1(31.52,91.4)
100OHM_MIPI_DSI_TX1_D0P_1: length 4.8
  TOP w0.092: J0501.26 29.88,94.55 30.46,93.97 31.53,93.97 31.62,93.87 D0502.3 31.62,93.28 31.5,93.15 R0572.2
100OHM_MIPI_DSI_TX1_D1N: length 64.8
  TOP w0.092: v1(28.55,91.42) 28.48,91.5 28.48,92.15 28.57,92.25 R0571.1 ; v1(51.05,68.62) 51.04,68.62 50.95,68.72 U1301.38
  INNER LAYER 3 w0.074: v1(28.55,91.42) 28.27,91.69 28.27,91.87 28.43,92.03 28.6,92.03 28.76,92.18 28.76,92.36 28.92,92.52 29.1,92.52 29.25,92.67 29.25,92.85 29.5,93.1 29.72,93.1 29.79,93.03 29.79,91.57 29.99,91.38 30.3,91.38 30.49,91.57 30.49,93.03 30.56,93.1 30.71,93.1 30.79,93.03 30.79,92.49 30.98,92.3 31.29,92.3 31.48,92.49 31.48,93.03 31.56,93.1 32.08,93.1 32.65,92.53 32.98,92.53 33.17,92.72 33.17,93.8 33.25,93.88 33.4,93.88 33.47,93.8 33.47,92.72 33.66,92.53 38.19,92.53 44,86.72 44,75.24 44.13,75.11 44.4,75.11 44.62,75.32 44.72,75.32 44.83,75.22 44.83,75.11 44.61,74.9 44.61,74.63 44.84,74.41 45.11,74.41 45.47,74.77 45.57,74.77 45.68,74.66 45.68,74.56 45.32,74.2 45.32,73.93 45.54,73.7 45.81,73.7 46.17,74.07 46.27,74.07 46.38,73.96 46.38,73.86 46.02,73.5 46.02,73.22 46.24,73 46.51,73 46.87,73.37 46.98,73.37 47.08,73.26 47.08,73.16 46.72,72.79 46.72,72.52 46.94,72.3 47.21,72.3 47.57,72.66 47.68,72.66 47.78,72.56 47.78,72.45 47.42,72.09 47.42,71.82 47.64,71.6 47.8,71.6 47.88,71.53 47.88,70.67 48.07,70.47 48.38,70.47 48.57,70.67 48.57,71.53 48.65,71.6 48.8,71.6 48.87,71.53 48.87,70.67 49.06,70.47 49.38,70.47 49.57,70.67 49.57,71.53 49.64,71.6 49.79,71.6 49.86,71.53 49.86,70.67 50.05,70.47 50.37,70.47 50.56,70.67 50.56,71.53 50.63,71.6 50.77,71.6 51.23,71.13 51.23,70.96 51.39,70.8 51.57,70.8 51.85,70.52 51.85,70.24 51.72,70.11 51.72,69.89 51.85,69.76 51.85,69.42 51.57,69.14 51.39,69.14 51.23,68.99 51.23,68.81 v1(51.05,68.62)
100OHM_MIPI_DSI_TX1_D1N_1: length 4
  TOP w0.092: J0501.24 29.07,95.23 28.98,95.13 28.98,94.9 28.78,94.7 28.78,94.54 28.58,94.34 28.42,94.34 28.21,94.14 28.21,93.98 28.48,93.72 28.48,93.28 28.6,93.15 R0571.2
100OHM_MIPI_DSI_TX1_D1P: length 65.1
  TOP w0.092: R0570.1 27.82,92.25 27.93,92.15 D0512.1 27.93,91.53 v1(27.8,91.4) ; v1(51.67,68.42) 51.75,68.35 U1301.34
  INNER LAYER 3 w0.074: v1(51.67,68.42) 51.52,68.58 51.52,68.82 52.05,69.34 52.05,70.6 50.85,71.8 50.55,71.8 50.36,71.61 50.36,70.75 50.28,70.67 50.14,70.67 50.06,70.75 50.06,71.61 49.87,71.8 49.56,71.8 49.37,71.61 49.37,70.75 49.29,70.67 49.14,70.67 49.07,70.75 49.07,71.61 48.88,71.8 48.57,71.8 48.37,71.61 48.37,70.75 48.3,70.67 48.15,70.67 48.08,70.75 48.08,71.61 47.89,71.8 47.73,71.8 47.62,71.9 47.62,72.01 47.98,72.37 47.98,72.64 47.76,72.86 47.49,72.86 47.13,72.5 47.02,72.5 46.92,72.61 46.92,72.71 47.28,73.07 47.28,73.34 47.06,73.57 46.79,73.57 46.43,73.2 46.32,73.2 46.22,73.31 46.22,73.41 46.58,73.78 46.58,74.05 46.36,74.27 46.09,74.27 45.72,73.9 45.62,73.9 45.52,74.01 45.52,74.11 45.88,74.48 45.88,74.75 45.66,74.97 45.39,74.97 45.02,74.61 44.92,74.61 44.81,74.71 44.81,74.82 45.03,75.03 45.03,75.3 44.8,75.52 44.53,75.52 44.32,75.31 44.22,75.31 44.2,75.33 44.2,86.8 38.27,92.72 33.74,92.72 33.67,92.8 33.67,93.88 33.48,94.08 33.17,94.08 32.97,93.88 32.97,92.8 32.9,92.72 32.73,92.72 32.16,93.3 31.47,93.3 31.28,93.11 31.28,92.57 31.21,92.5 31.06,92.5 30.99,92.57 30.99,93.11 30.8,93.3 30.48,93.3 30.29,93.11 30.29,91.65 30.22,91.58 30.07,91.58 29.99,91.65 29.99,93.11 29.8,93.3 29.42,93.3 28.07,91.95 28.07,91.69 v1(27.8,91.4)
100OHM_MIPI_DSI_TX1_D1P_1: length 3.8
  TOP w0.092: R0570.2 27.81,93.15 27.93,93.27 D0512.3 27.93,93.72 28,93.8 28,94.22 28.77,94.99 28.77,95.13 28.68,95.22 J0501.23
100OHM_MIPI_DSI_TX1_D2N: length 63.1
  TOP w0.092: v1(54.25,68.62) 54.24,68.62 54.15,68.72 U1301.28 ; R0569.1 24.9,92.25 24.77,92.12 D0511.2 24.77,91.5 v1(24.88,91.4)
  INNER LAYER 3 w0.074: v1(24.88,91.4) 24.61,91.66 24.61,91.85 24.45,92 24.45,92.18 24.3,92.34 24.12,92.34 23.9,92.56 23.9,92.88 24.03,93.01 24.03,93.23 23.9,93.35 23.9,93.58 24.06,93.73 24.24,93.73 24.39,93.89 24.39,94.07 24.8,94.47 25.1,94.47 25.18,94.4 25.18,92.84 25.37,92.65 25.68,92.65 25.87,92.84 25.87,94.4 25.95,94.47 26.1,94.47 26.17,94.4 26.17,92.84 26.36,92.65 26.68,92.65 26.87,92.84 26.87,94.4 26.94,94.47 28.32,94.47 28.45,94.6 34.73,94.6 35,94.33 38.22,94.33 46.35,86.2 46.35,75.84 49.32,72.88 54.22,72.88 54.4,72.69 54.4,71.83 54.27,71.7 54.27,71.48 54.4,71.35 54.4,71.13 54.27,71 54.27,70.78 54.4,70.66 54.4,70.43 54.27,70.31 54.27,70.09 54.4,69.96 54.4,69.74 54.27,69.61 54.27,69.39 54.4,69.26 54.4,69.04 54.48,68.97 54.48,68.85 v1(54.25,68.62)
100OHM_MIPI_DSI_TX1_D2N_1: length 5.9
  TOP w0.092: R0569.2 24.9,93.15 24.77,93.28 D0511.4 24.77,93.85 24.82,93.89 26.51,93.89 26.76,94.14 26.93,94.14 27.12,94.33 27.12,94.5 27.32,94.7 27.48,94.7 27.68,94.89 27.68,95.06 27.88,95.25 J0501.21
100OHM_MIPI_DSI_TX1_D2P: length 63.1
  TOP w0.092: v1(54.88,68.42) 54.95,68.35 U1301.24 ; R0568.1 24.1,92.25 24.23,92.12 D0511.1 24.23,91.47 v1(24.18,91.42)
  INNER LAYER 3 w0.074: v1(54.88,68.42) 54.67,68.62 54.67,69.05 54.6,69.12 54.6,72.78 54.3,73.08 49.4,73.08 46.55,75.92 46.55,86.28 38.31,94.53 35.08,94.53 34.81,94.8 28.37,94.8 28.24,94.67 26.86,94.67 26.67,94.48 26.67,92.92 26.59,92.85 26.44,92.85 26.37,92.92 26.37,94.48 26.18,94.67 25.87,94.67 25.67,94.48 25.67,92.92 25.6,92.85 25.45,92.85 25.38,92.92 25.38,94.48 25.19,94.67 24.72,94.67 23.7,93.66 23.7,92.47 24.41,91.76 24.41,91.66 v1(24.18,91.42)
100OHM_MIPI_DSI_TX1_D2P_1: length 5.9
  TOP w0.092: J0501.20 27.48,95.15 26.43,94.1 24.62,94.1 24.23,93.7 D0511.3 24.23,93.25 24.12,93.15 R0568.2
100OHM_MIPI_DSI_TX1_D3N: length 59.5
  TOP w0.092: v1(55.85,68.62) 55.84,68.62 55.75,68.72 U1301.23 ; R0567.1 21.19,92.25 21.07,92.13 D0514.2 21.07,91.42 v1(21.12,91.38)
  INNER LAYER 3 w0.074: v1(55.85,68.62) 56.05,68.83 56.2,68.83 56.27,68.9 56.27,71.72 54.49,73.5 49.57,73.5 46.98,76.09 46.98,86.5 38.15,95.33 27.9,95.33 27.75,95.17 24.13,95.17 20.9,91.95 20.9,91.6 v1(21.12,91.38)
100OHM_MIPI_DSI_TX1_D3N_1: length 9.5
  TOP w0.092: J0501.18 26.68,95.3 26.56,95.18 26.56,95.01 26.27,94.72 25.99,94.72 25.87,94.6 25.59,94.6 25.48,94.72 25.2,94.72 25.08,94.6 24.81,94.6 24.69,94.72 24.41,94.72 24.3,94.6 24.02,94.6 23.9,94.72 23.62,94.72 23.51,94.6 23.23,94.6 23.11,94.72 22.84,94.72 22.72,94.6 22.44,94.6 22.32,94.72 22,94.72 21.88,94.6 21.61,94.6 21.49,94.72 21.21,94.72 20.91,94.41 20.91,93.89 21.07,93.72 D0514.4 21.07,93.24 21.17,93.15 R0567.2
100OHM_MIPI_DSI_TX1_D3P: length 60.1
  TOP w0.092: U1301.19 56.55,68.35 v1(56.48,68.42) ; v1(20.48,91.38) 20.52,91.42 20.52,92.13 20.41,92.25 R0566.1
  INNER LAYER 3 w0.074: v1(20.48,91.38) 20.7,91.6 20.7,92.03 24.04,95.38 27.67,95.38 27.82,95.53 38.23,95.53 47.17,86.58 47.17,76.18 49.65,73.7 54.58,73.7 56.48,71.8 v1(56.48,68.42)
100OHM_MIPI_DSI_TX1_D3P_1: length 8.9
  TOP w0.092: J0501.17 26.27,95.3 26.35,95.23 26.35,95.1 26.18,94.92 21.13,94.92 20.7,94.49 20.7,93.89 20.52,93.72 20.52,93.25 20.43,93.15 R0566.2
CAM0_AVDD: length 24.6
  TOP w0.3: J0201.16 92.95,95.25 93.08,95.38 v1(93.08,96.75)
  INNER LAYER 2 w0.3: v1(76.83,94.58) 77.15,94.9 77.15,98.1 77.75,98.7 82.05,98.7 82.35,99 82.8,99 83.1,98.7 92.72,98.7 93.15,98.28 93.15,96.83 v1(93.08,96.75)
  BOTTOM w0.3: v1(76.83,94.58) B0201.2
CAM0_DOVDD_1V8: length 25.3
  TOP w0.2: v1(93.95,98.65) 93.92,98.67 93.12,98.67 92.65,98.2 J0201.17
  BOTTOM w0.2: B0205.2 74.83,94.15 75.55,94.88 75.55,97.8 76.55,98.8 82.22,98.8 82.38,98.95 82.78,98.95 82.92,98.8 93.8,98.8 v1(93.95,98.65)
CAM0_PDN_L_GPIO3_D5: length 78.8
  TOP w0.1: J0201.24 v1(90.55,95.5) ; v1(99.4,82.25) 99.31,82.16 99.31,72.94 96.67,70.3 96.67,63.23 90.9,57.45 90.9,55.08 84.15,48.33 71,48.33 70.25,47.58 70.25,44.77 69.47,44 69.47,43.67 68.47,42.67 U1301.316
  INNER LAYER 3 w0.1: v1(90.55,95.5) 90.55,95.22 91.55,94.22 93.3,94.22 95.45,92.08 95.45,90.92 99.17,87.2 99.17,82.47 v1(99.4,82.25)
CAM0_RST_L_GPIO3_D4: length 78.6
  TOP w0.1: v1(98.55,79.88) 98.8,79.62 98.8,73.03 96.22,70.45 96.22,63.45 90.5,57.73 90.5,55.27 83.96,48.74 70.81,48.74 69.85,47.77 69.85,45 69.06,44.21 69.06,43.86 68.67,43.48 U1301.317 ; v1(93.67,95.53) 93.67,95.45 93.55,95.33 J0201.14
  INNER LAYER 3 w0.1: v1(93.67,95.53) 93.67,95.45 100.03,89.1 100.03,81.2 98.7,79.88 v1(98.55,79.88)
CAM1_AVDD: length 5.6
  TOP w0.3: 82.28,94.88 82.28,95.9 v1(82.08,96.1)
  BOTTOM w0.3: B0204.2 78.47,94.6 78.47,94.72 79.28,95.53 80.97,95.53 81.55,96.1 v1(82.08,96.1)
CAM1_DOVDD_1V8: length 11.6
  TOP w0.2: v1(82.03,97) 82.03,97.7 J0202.17
  BOTTOM w0.2: v1(82.03,97) 80.6,98.42 76.85,98.42 75.85,97.42 75.85,94.58 75.67,94.4 B0206.2
CAM1_MCLK: length 102.7
  TOP w0.1: v1(69.53,85.22) 71.83,85.22 73.33,86.72 75.03,86.72 76.35,88.05 76.35,93.17 77.03,93.85 78,93.85 78.22,94.08 78.22,95.2 v1(77.95,95.47) ; v1(78.65,72.03) 78.65,72.08 78.85,72.28 85.17,72.28 89.47,76.58 89.47,80.88 v1(89.7,81.1) ; v1(41.92,63.8) 40.52,63.8 39.65,64.67 38.85,64.67 38.15,65.38 U1301.75
  INNER LAYER 3 w0.1: v1(69.53,85.22) 69.78,85.22 73.72,81.28 80.51,81.28 81.06,80.72 89.33,80.72 v1(89.7,81.1) ; v1(41.92,63.8) 57.27,63.8 60.24,66.76 64.37,66.76 68.83,71.22 72.96,71.22 74.66,72.92 77.5,72.92 78.4,72.03 v1(78.65,72.03)
  BOTTOM w0.1: R0226.1 v1(77.95,95.47)
CAM1_PDN_L_GPIO3_D3: length 91.9
  TOP w0.1: U1301.313 67.1,42.67 67.7,43.27 68.78,43.27 69.28,43.77 69.28,44.1 70.05,44.88 70.05,47.67 70.9,48.52 84.05,48.52 90.7,55.17 90.7,57.6 96.45,63.35 96.45,70.38 99.03,72.95 99.03,81.65 v1(98.35,82.33) ; J0202.24 v1(79.88,94.17)
  INNER LAYER 3 w0.1: v1(98.35,82.33) 97.6,82.33 97.42,82.5 95.8,82.5 95.33,82.97 95.33,84.15 95.83,84.65 95.83,87.2 89.28,93.75 83.42,93.75 82.3,94.88 80.58,94.88 v1(79.88,94.17)
CAM1_RST_L_GPIO3_D2: length 89.7
  TOP w0.1: J0202.14 v1(82.88,95.55) ; U1301.314 65.33,43.48 65.55,43.7 65.55,44.12 65.78,44.35 67.22,44.35 67.72,44.85 69.25,44.85 69.45,45.05 69.45,47.7 70.72,48.98 83.9,48.98 90.3,55.37 90.3,57.83 96.03,63.55 96.03,70.6 97.7,72.28 97.7,82.65 v1(98.05,83)
  INNER LAYER 3 w0.1: v1(98.05,83) 97.5,83 97.2,82.7 95.9,82.7 95.53,83.08 95.53,83.95 96.05,84.47 96.05,87.28 89.38,93.95 85.25,93.95 84.05,95.15 83.62,95.15 83.22,95.55 v1(82.88,95.55)
CAM_DOVDD_1V8: length 28.1
  INNER LAYER 2 w0.2: v1(82.5,96.55) 82.5,97.78 83.08,98.35 87.28,98.35 87.47,98.15 v1(87.47,96.6)
  BOTTOM w0.1: B0205.1 R0212.2 C0299.1
  BOTTOM w0.2: R0222.2 R0221.2 R0207.2 R0208.2 87.75,96.88 v1(87.47,96.6) ; B0206.1 76.25,93.53 76.25,97.3 77.05,98.1 80.5,98.1 81.47,97.13 81.47,96.75 81.67,96.55 v1(82.5,96.55)
  BOTTOM w0.4: U0205.5 C0209.2 B0205.1 B0206.1
CEC_HDMI: length 12.1
  TOP w0.1: v1(8.1,12.45) 8.2,12.35 J0401.13
  BOTTOM w0.1: D0404.3 13.05,18.23 R0416.1 12.4,17.88 12.05,17.52 D0408.1 8.72,14.5 8.2,13.97 8.2,12.55 v1(8.1,12.45)
CMA0_MCLK: length 90.1
  TOP w0.1: v1(90.25,96.95) J0201.25 ; v1(95.97,83.53) 95.97,83.47 95.2,82.7 95.2,72.33 94.58,71.7 94.58,64.22 82.22,51.88 73.97,51.88 73.55,51.45 71.2,51.45 70.38,50.62 v1(70.38,50.25) ; U1301.279 v1(56.55,39.45)
  INNER LAYER 3 w0.1: v1(70.38,50.25) 70.05,50.25 69.2,49.4 64.7,49.4 61.92,46.62 61.92,44.95 56.55,39.58 v1(56.55,39.45) ; v1(90.25,96.95) 89.55,96.25 89.55,95.03 98.08,86.5 98.08,84 97.6,83.53 v1(95.97,83.53)
DBG_RXD: length 69.9
  TOP w0.1: J1201.23 113.42,89.72 110.25,89.72 109,88.47 90.35,88.47 88.21,86.34 88.21,77.29 85.29,74.36 73.89,74.36 71.72,72.2 70.74,72.2 69.34,70.8 67.42,70.8 66.65,70.03 65.72,70.03 63.02,67.33 63.02,65.1 62.65,64.72 U1301.378
DBG_TXD: length 71.2
  TOP w0.1: J1201.21 D1255.2 110.38,89.12 109.95,89.12 109.1,88.28 90.45,88.28 88.42,86.25 88.42,77.2 85.38,74.15 74.08,74.15 71.92,72 70.83,72 69.42,70.6 67.53,70.6 66.75,69.83 65.8,69.83 63.23,67.25 63.23,65.1 63.45,64.88 63.45,62.83 63.3,62.67 U1301.374
DC12V: length 154.5
  TOP w0.1: v1(50,86.53) 50.2,86.33 v1(50.2,82.25)
  TOP w0.2: v1(32.75,65.33) 33.8,64.28 v1(36.48,64.28) ; v1(22.75,86.95) v1(23.25,86.95)
  TOP w0.5: v1(10.3,82.58) 9.7,82.58 8.7,83.58 R0116.1 ; v1(10.8,82.58) 11.3,83.08 TP0102.1
  TOP w0.8: 3.5,45.45 6.95,48.9 6.95,79.03 10.12,82.2
  TOP w4: 24.95,86.6 25.57,85.97 42.48,85.97
  BOTTOM w0.1: R0113.2 v1(50.2,82.25) ; R0620.2 36.08,52.05 36.73,52.7 40.45,52.7 40.67,52.48
  BOTTOM w0.2: 24.57,86 24.55,85.97 24.55,82.95 25.27,82.22 R0104.2 ; R0117.2 v1(32.75,65.33) ; R0723.2 65.35,30.82 63.55,30.82 61.22,33.16 61.22,33.44
  BOTTOM w2: 40.9,49.73 40.88,49.7 ; 16.85,77.08 16.85,73.45
  BOTTOM w3: 37.52,66.55 37.52,69.83 41.5,73.8 41.5,83.33 ; 62.34,34.56 57.38,29.6 41.85,29.6 ; 37.83,39.03 40.95,42.15 40.95,48.83 ; 40.67,60.23 40.67,49.95
  vias: v1(3.3,45.45) v1(3.3,44.95) v1(22.75,87.45) v1(22.75,86.45) v1(22.75,85.95) v1(23.25,87.45) v1(23.25,86.45) v1(23.25,85.95) v1(40.67,84.9) v1(40.7,84.4) v1(41.17,84.9) v1(41.2,84.4) v1(41.67,84.9) v1(41.7,84.4) v1(50,87.03) v1(50.5,87.03) v1(50.5,86.53) v1(51,87.03) v1(51,86.53)
EDP_BL_EN: length 16.4
  BOTTOM w0.1: R0522.1 D0505.3 9.35,33.8 8.97,34.17 7.75,34.17 7.58,34 7.15,34 6.83,34.33 6.83,35.05 7.16,35.38 7.16,39.81 7.4,40.05 7.4,41.7 7.16,41.94 7.16,42.64 7.89,43.38 9.32,43.38
EDP_DET: length 68.8
  TOP w0.1: U1301.70 39.75,65.15 40.3,64.6 v1(41.17,64.6) ; v1(25.7,31.05) 23.82,31.05 v1(20.88,34)
  INNER LAYER 3 w0.1: v1(20.88,34) 20,34 15.53,38.48 15.53,41.58 16.98,43.02 16.98,44.38 v1(16.5,44.85) ; v1(42.77,53.88) 42.77,53.77 41.92,52.92 36.33,52.92 34.95,51.55 34.95,50.9 27,42.95 27,42.42 26.75,42.17 26.55,42.17 26.43,42.05 26.43,32.12 25.7,31.4 v1(25.7,31.05)
  BOTTOM w0.1: R0527.2 R0516.2 v1(16.5,44.85) ; v1(42.77,53.88) 42.77,61.02 41.17,62.62 v1(41.17,64.6)
EDP_HPD: length 3.3
  BOTTOM w0.1: 11.72,43.88 14.43,43.88 14.55,44 R0527.1
EDP_PWM: length 9.9
  BOTTOM w0.1: 10.32,35.27 9.32,35.27 9.32,35.67 7.88,37.12 7.88,41.95 8.3,42.38 9.32,42.38
EDP_VDDIN: length 9.2
  BOTTOM w0.1: 14.5,35.35 Q0501.3 13.95,35.3 13.47,34.83 12.78,34.83 12.75,34.85 R0525.2 12.2,34.9 12.57,35.27 R0506.2 R0522.2 ; 11.72,39.88 11.72,38.88 11.22,39.38 9.32,39.38
EDP_VLED: length 1.5
  BOTTOM w0.4: 9.32,52.38 7.8,52.38
ETH1_REFCLKO_25M_M1: length 75.6
  TOP w0.1: v1(112.4,41.2) 113.85,42.65 113.85,49.73 108.5,55.08 107.75,55.08 106.8,56.02 99.17,56.02 98.47,55.33 92.55,55.33 89.67,52.45 89.67,50 87.22,47.55 72.45,47.55 v1(72.15,47.25) ; U1301.288 v1(59.75,39.42)
  INNER LAYER 3 w0.1: v1(72.15,47.25) 71.97,47.25 71.2,46.48 68.5,46.48 62.3,40.27 60.6,40.27 v1(59.75,39.42)
  BOTTOM w0.1: R0925.2 v1(112.4,41.2)
EXT_EN: length 188.5
  TOP w0.1: v1(20.23,28.38) 20.23,27.77 25.43,22.57 25.7,22.57 v1(25.9,22.77) ; U1301.217 35.75,37.38 v1(35.58,37.55) ; v1(52.4,82.42) 52.4,82.25 51.67,81.53 47.8,81.53 46.27,83.05 32.6,83.05 30.43,80.88 15.8,80.88 12.75,83.92 12.75,85.1 11.43,86.42 7.22,86.42 6.17,85.38 6.17,52.95 2.12,48.9 2.12,43.85 6.7,39.27 6.7,30.8 7.25,30.25 7.25,29.62 7.12,29.5 v1(7.12,28.98)
  INNER LAYER 2 w0.1: v1(28.27,38.2) 28.35,38.2 28.82,37.73 34.5,37.73 34.73,37.95 35.17,37.95 v1(35.58,37.55)
  INNER LAYER 3 w0.1: v1(20.23,28.38) 20.23,28.57 19.73,29.07 7.22,29.07 v1(7.12,28.98)
  BOTTOM w0.1: R0644.2 33.08,49.02 28.38,44.33 28.38,38.3 v1(28.27,38.2) 27.95,37.88 27.95,31.9 27.18,31.12 27.18,26.32 26.45,25.6 26.45,23.05 26.18,22.77 v1(25.9,22.77)
  BOTTOM w0.2: R0166.2 51.85,82.42 v1(52.4,82.42) 54.75,82.42 55.12,82.8 62.33,82.8 62.98,83.45
FSPI_CS0N/FLASH_CS0N: length 63.3
  TOP w0.1: U1301.281 v1(55.75,33.85) ; v1(92.83,55.92) 92.8,55.95 92.58,55.95 89.25,52.62 89.25,50.17 87.03,47.95 71.5,47.95 71.03,47.48 v1(71.03,47.2)
  INNER LAYER 3 w0.1: v1(71.03,47.2) 70.75,46.92 68.28,46.92 62.23,40.88 60.17,40.88 59.15,39.85 59.15,37.33 58.85,37.02 57.45,37.02 56.73,37.75 56.33,37.75 55.75,37.17 v1(55.75,33.85)
  BOTTOM w0.1: R1125.2 99.45,56.85 98.33,55.73 93.03,55.73 v1(92.83,55.92)
FSPI_D0/FLASH_RDY: length 135.1
  TOP w0.1: U1301.267 51.75,33.95 51.85,33.85 53.02,33.85 53.35,33.52 53.35,31.82 53.65,31.52 55.25,31.52 62.67,24.1 64.55,24.1 v1(64.72,24.27) ; v1(12.62,5.4) 13.1,5.88 23.82,5.88 26.45,3.25 28.35,3.25 29.02,2.58 30.25,2.58 31,3.33 53.48,3.33 55.65,1.15 61.35,1.15 62.2,2 62.2,16.48 59.65,19.02 v1(59.65,19.57) ; v1(7.47,32.77) 7.53,32.73 7.53,28.65 7.2,28.32 7.2,26.6 1.32,20.73 1.32,14.07 v1(2.21,13.19)
  INNER LAYER 3 w0.1: v1(64.72,24.27) 60.02,19.57 v1(59.65,19.57) ; v1(2.21,13.19) 3.98,11.43 3.98,10.12 8.78,5.33 12.55,5.33 v1(12.62,5.4)
  BOTTOM w0.1: D0505.1 v1(7.47,32.77)
GMAC1_MDC_M1: length 50.2
  TOP w0.1: v1(72.8,45.42) 73.05,45.17 75.4,45.17 75.72,44.85 85.55,44.85 v1(85.7,45) ; U1301.290 v1(59.02,34.77)
  INNER LAYER 3 w0.1: v1(59.02,34.77) 61.3,37.05 61.3,37.55 62.06,38.31 63.24,38.31 69.2,44.27 71.7,44.27 72.8,45.38 v1(72.8,45.42) ; v1(98.08,38.25) 96.6,38.25 96.05,38.8 95.67,38.8 95.25,38.38 91.72,38.38 85.92,44.17 85.92,44.77 v1(85.7,45)
  BOTTOM w0.1: v1(98.08,38.25) 98.08,38.62 98.92,39.48 R0931.2
GMAC1_MDIO_M1: length 50.3
  TOP w0.1: v1(57.4,34.77) U1301.286 ; v1(86.3,45.15) 86.03,45.42 85.53,45.42 85.15,45.05 75.83,45.05 75.5,45.38 73.65,45.38 v1(73.38,45.65)
  INNER LAYER 3 w0.1: v1(73.38,45.65) 73.17,45.85 72.62,45.85 72.38,45.6 72.38,45.25 71.62,44.5 69.1,44.5 63.15,38.55 62.02,38.55 61.1,37.63 61.1,37.15 59.15,35.2 57.9,35.2 57.48,34.77 v1(57.4,34.77) ; v1(86.3,45.15) 86.15,45 86.15,44.25 91.83,38.58 95.1,38.58 95.55,39.02 96.4,39.02 v1(96.5,38.92)
  BOTTOM w0.1: R0949.2 97.15,39.55 96.53,38.92 v1(96.5,38.92)
GPIO1_D4: length 50.5
  TOP w0.1: v1(74.78,54.77) 74.78,55.15 76.92,57.3 81.18,57.3 84.8,60.92 v1(85.15,60.92) ; U1301.277 v1(54.95,35.65)
  INNER LAYER 3 w0.1: v1(54.95,35.65) 54.95,37.02 56.15,38.23 56.6,38.23 57.5,37.33 58.83,37.33 58.95,37.45 58.95,40.05 60.08,41.17 62.2,41.17 65,43.98 65,46.75 66.15,47.9 69.92,47.9 70.62,48.6 73.68,48.6 75.08,50 75.08,54.4 74.78,54.7 v1(74.78,54.77)
  BOTTOM w0.1: R0721.1 v1(85.15,60.92)
GPIO3_A4: length 66.8
  TOP w0.1: v1(88.5,66.38) 88.38,66.25 85.53,66.25 82.3,63.02 80.3,63.02 77.5,60.23 74.58,60.23 69.03,54.67 U1301.352
  INNER LAYER 3 w0.1: J1201.10 115.72,77.83 113.2,77.83 111.67,76.3 111.67,69.91 109.92,68.15 106.32,68.15 104.77,69.7 102.35,69.7 98.08,65.42 92.85,65.42 92.12,66.15 88.72,66.15 v1(88.5,66.38)
  BOTTOM w0.1: v1(88.5,66.38) D0703.1
GPIO3_A7: length 67.1
  TOP w0.1: U1301.347 67.25,53.08 67.33,53.15 68.78,53.15 69.19,53.56 69.19,54.24 74.78,59.83 77.72,59.83 80.47,62.58 82.5,62.58 85.65,65.72 89.35,65.72 v1(90.17,66.55)
  INNER LAYER 3 w0.1: v1(90.17,66.55) 90.5,66.55 90.65,66.4 92.2,66.4 92.97,65.62 97.99,65.62 102.27,69.9 104.86,69.9 106.41,68.35 109.83,68.35 111.47,69.99 111.47,76.4 113.1,78.03 115.72,78.03 J1201.12
GPIO3_D0: length 28.8
  TOP w0.1: v1(74.35,55.27) 74.58,55.27 76.85,57.55 80.35,57.55 v1(80.6,57.8) ; U1301.318 v1(63.7,44.27)
  INNER LAYER 3 w0.1: v1(74.35,55.27) 74.35,54.6 74.83,54.12 74.83,50.05 73.58,48.8 70.5,48.8 69.85,48.15 65.8,48.15 63.7,46.05 v1(63.7,44.27)
  BOTTOM w0.1: D0701.1 v1(80.6,57.8)
GPIO3_D1: length 94.9
  TOP w0.1: v1(26.65,26.48) 23.8,26.48 19.8,30.48 v1(19.8,31.23) ; v1(58.58,45.92) 59.42,45.08 U1301.319
  INNER LAYER 2 w0.1: v1(38.6,54.25) 38.95,54.6 43.5,54.6 v1(43.9,54.2)
  INNER LAYER 3 w0.1: v1(6.58,40.6) 6.88,40.3 6.88,32.35 8.5,30.73 19.3,30.73 v1(19.8,31.23) ; v1(43.9,54.2) 50.3,54.2 v1(58.58,45.92)
  BOTTOM w0.1: v1(6.58,40.6) D0503.1 ; D0507.1 19.48,31.55 v1(19.8,31.23) ; v1(38.6,54.25) 37.52,53.17 36.33,53.17 34.77,51.62 34.77,51.05 28.18,44.45 28.18,38.7 27.75,38.27 27.75,32 26.9,31.15 26.9,26.73 v1(26.65,26.48)
GPIO4_B2: length 63.8
  TOP w0.1: U1301.291 60.55,37.38 v1(60.7,37.52) ; v1(73.97,45.77) 74.12,45.62 75.58,45.62 75.95,45.25 85.05,45.25 85.44,45.64 87.21,45.64 91,49.42 91,51.85 93.1,53.95 99.03,53.95 99.75,54.67 106.22,54.67 107.2,53.7 107.45,53.7 107.85,53.3 107.85,52.42 108.22,52.05 v1(109.78,52.05)
  INNER LAYER 3 w0.1: v1(60.7,37.52) 61.95,38.77 63,38.77 68.92,44.7 71.5,44.7 72.15,45.35 72.15,45.67 72.55,46.08 73.67,46.08 v1(73.97,45.77)
  BOTTOM w0.1: D0902.3 110.75,50.1 110.35,50.5 R0935.1 R0941.2 109.95,52.05 v1(109.78,52.05)
GPIO4_C2: length 42.2
  TOP w0.1: v1(62.27,37.85) 60.77,39.35 60.77,42.25 57.85,45.17 v1(57.85,47.5) ; U1301.376 v1(65.58,62.67)
  INNER LAYER 2 w0.1: v1(62.27,37.85) 62.12,37.85 61.55,37.27 61.55,36.62 60.58,35.65 60.58,34.08 60.75,33.9 64.33,33.9 64.58,33.65 64.58,32.45 v1(65.05,31.98)
  INNER LAYER 3 w0.1: v1(57.85,47.5) 57.85,49.38 65.58,57.1 v1(65.58,62.67)
  BOTTOM w0.1: R0726.1 65.2,32.12 v1(65.05,31.98)
HDMI14_TX_PWREN_H_GPIO0_D5: length 99.9
  TOP w0.1: U1301.80 36.92,65.67 37.23,65.38 37.23,64.9 38,64.12 39.52,64.12 41.05,62.6 41.75,62.6 v1(42.12,62.98) ; v1(90.1,79.62) 90.1,76.45 85.53,71.88 80.72,71.88 v1(80.08,71.22) ; v1(66.67,85.65) 66.78,85.75 66.78,85.95 66.08,86.65 66.08,89.78 67.03,90.72 67.03,92.79 66.71,93.1 v1(66.55,93.1)
  INNER LAYER 3 w0.1: v1(42.12,62.98) 57.08,62.98 60.46,66.36 64.54,66.36 69,70.83 73.25,70.83 74.65,72.22 77.22,72.22 78.22,71.22 v1(80.08,71.22) ; v1(90.1,79.62) 90.08,79.65 89.4,79.65 89.15,79.9 73.25,79.9 68.03,85.12 67.2,85.12 v1(66.67,85.65)
  BOTTOM w0.1: v1(66.55,93.1) Q0402.1
HDMI_5V: length 18.5
  TOP w0.25: J0401.18 v1(5.7,12.43)
  BOTTOM w0.5: R0408.2 7.12,26.27 6.8,25.95 D0403.1 6.78,24.95 C0413.2 5.08,24.2 4.08,23.2 4.08,14.53 5.7,12.9 v1(5.7,12.43)
HDMI_TX_HPD_PORT: length 8.6
  TOP w0.1: J0401.19 5.2,12.07 4.88,12.4 v1(4.78,12.4)
  BOTTOM w0.1: R0401.1 R0425.1 D0410.1 2.85,14.32 v1(4.78,12.4)
HDMI_TX_HPDIN: length 170.9
  TOP w0.1: v1(29.23,4.62) 29.23,5.03 28.02,6.22 26.15,6.22 25.85,6.53 v1(12,6.53) ; U1301.379 v1(67.47,63.48)
  INNER LAYER 2 w0.1: v1(90.85,32.58) 90.97,32.45 90.97,26.48 90.88,26.38 v1(90.47,26.38)
  INNER LAYER 3 w0.1: v1(90.47,26.38) 90.35,26.25 90,26.25 81.17,17.43 81.17,5.42 80,4.25 59.83,4.25 57.53,1.95 42.35,1.95 40.1,4.2 31.85,4.2 31,5.05 29.65,5.05 v1(29.23,4.62) ; v1(67.47,63.48) 67.9,63.48 71.75,59.62 74.25,59.62 77.55,56.33 77.55,46.8 90.7,33.65 90.7,32.73 v1(90.85,32.58) ; v1(12,6.53) 12,7.08 11.5,7.58 11.5,18.5 11.1,18.9 9.03,18.9 8.55,19.38 v1(1.95,19.38)
  BOTTOM w0.1: R0401.2 v1(1.95,19.38)
HDMITX_CEC_M0: length 164.5
  TOP w0.1: U1301.382 v1(67.47,65.08) ; v1(13.5,7.33) 13.7,7.12 26.15,7.12 26.4,6.88 28.3,6.88 30.27,4.9 30.52,4.9 v1(30.77,4.65)
  INNER LAYER 2 w0.1: v1(91.1,33.15) 91.25,33 91.25,26.3 v1(90.9,25.95)
  INNER LAYER 3 w0.1: v1(30.77,4.65) 31.1,4.65 31.75,4 40,4 42.25,1.75 57.62,1.75 59.92,4.05 80.08,4.05 81.38,5.34 81.38,17.32 89.97,25.93 90.88,25.93 v1(90.9,25.95) ; v1(13.5,7.33) 13.5,11.82 14.47,12.8 14.47,18.9 15.43,19.85 v1(15.43,20.93) ; v1(67.47,65.08) 67.47,64.28 71.88,59.87 74.29,59.87 77.75,56.41 77.75,46.9 90.92,33.73 90.92,33.33 v1(91.1,33.15)
  BOTTOM w0.1: D0404.2 14.55,20.67 14.55,20.68 R0428.1 15.25,21.1 v1(15.43,20.93)
HDMITX_SCL: length 171.7
  TOP w0.1: U1301.387 v1(69.22,68.28) ; v1(13.1,7.78) 13.1,7.12 13.3,6.92 26.05,6.92 26.3,6.67 28.18,6.67 30.2,4.65 v1(30.2,4.47)
  INNER LAYER 2 w0.1: v1(91.55,34.3) 91.65,34.3 91.75,34.2 91.75,32.58 91.65,32.48 91.65,25.77 v1(91,25.12)
  INNER LAYER 3 w0.1: v1(91.55,34.3) 91.5,34.25 91,34.25 78.15,47.1 78.15,56.58 74.45,60.27 72.1,60.27 68.15,64.22 68.15,67.2 v1(69.22,68.28) ; v1(13.1,7.78) 13.3,7.97 13.3,11.95 14.28,12.93 14.28,18.88 13.85,19.3 12.43,19.3 11.75,19.98 v1(11.75,20.93) ; v1(91,25.12) 89.78,25.12 81.78,17.12 81.78,5.17 80.25,3.65 60.08,3.65 57.78,1.35 42.05,1.35 39.8,3.6 30.68,3.6 30.2,4.08 v1(30.2,4.47)
  BOTTOM w0.1: U0413.2 11.13,20.64 11.12,20.65 R0405.1 11.6,21.07 v1(11.75,20.93)
